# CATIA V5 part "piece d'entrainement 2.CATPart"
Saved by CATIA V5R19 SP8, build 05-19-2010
Part number: piece d'entrainement 2
Bounding box of the stored display mesh (mm): x -59.975 to 59.975, y 0 to 550, z -59.975 to 59.975
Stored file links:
  G:\EU_thinkMotion\CFAO_2010\MMS_groupe2\MMS_groupe2\A reprendre\splanchenault\Planchenault\piece d'entrainement 2.CATPart
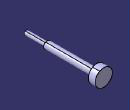
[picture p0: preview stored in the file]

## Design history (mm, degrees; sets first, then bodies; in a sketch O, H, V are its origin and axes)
Body1 (main body)
  Sketch1 on yz-plane, origin (0, 0, 0), H (0, 1, 0), V (0, 0, 1)
    line L1 (0, 0) -> (0, 15)
    line L2 (0, 15) -> (150, 15)
    line L3 (150, 15) -> (150, 25)
    line L4 (150, 25) -> (500, 25)
    line L5 (500, 25) -> (500, 60)
    line L6 (500, 60) -> (550, 60)
    line L7 (550, 60) -> (550, 0)
    line L8 (550, 0) -> (0, 0)
    length L1 = 15
    length L3 = 10
    length L5 = 35
    length L6 = 50
    length L4 = 350
    length L2 = 150
    vertical: L1 V, L3 V, L5 V, L7 V
    horizontal: L2 H, L4 H, L6 H, L8 H
  Shaft1: profile Sketch1, axis Sketch1.L8, angle 360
